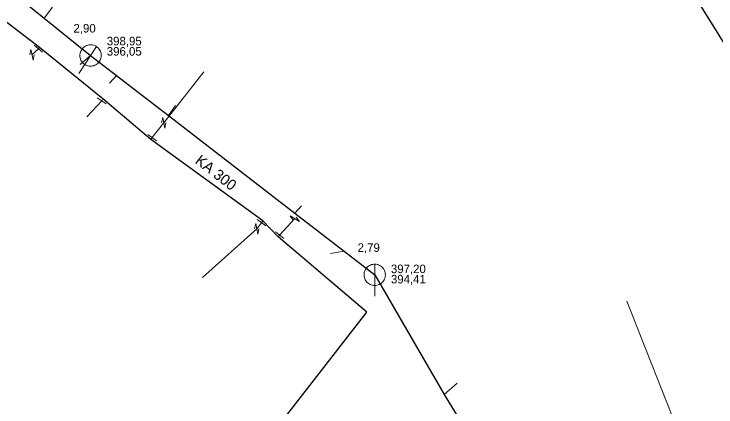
# Model space of a CAD drawing. Extents: x -809028 to -807737, y -990545 to -989489.
# Drawn here: x -808618 to -808552.3, y -989965.3 to -989928.5 of the extents above; entities that cross this region are included whole.
import ezdxf

# ---------------------------------------------------------------- set-up
doc = ezdxf.new("R2010")
doc.units = 0
doc.header["$LTSCALE"] = 0.32
for name, color, linetype, lineweight in [('1', 7, 'Continuous', 13), ('11', 7, 'Continuous', 13), ('13', 7, 'Continuous', 13), ('14', 7, 'Continuous', 25), ('17', 7, 'Continuous', 25), ('22', 7, 'Continuous', 13), ('34', 7, 'Continuous', 13), ('47', 7, 'Continuous', 13)]:
    doc.layers.add(name, color=color, linetype=linetype, lineweight=lineweight)

msp = doc.modelspace()

# ---------------------------------------------------------------- linework, layer by layer
at = {"layer": '11'}
for p, q in [((-808614.441, -989927.888), (-808615.221, -989928.912)), ((-808611.855, -989933.254), (-808610.879, -989932.412)), ((-808609.092, -989934.993), (-808608.456, -989934.281)), ((-808602.923, -989937.094), (-808603.589, -989938.035)), ((-808591.103, -989946.477), (-808591.739, -989947.173)), ((-808588.406, -989950.943), (-808587.127, -989950.728)), ((-808576.519, -989963.089), (-808577.742, -989964.137))]:
    msp.add_line(p, q, dxfattribs=at)
at = {"layer": '13'}
for p, q in [((-808615.761, -989931.774), (-808616.368, -989932.337)), ((-808604.02, -989938.699), (-808600.261, -989933.936)), ((-808609.837, -989936.655), (-808611.215, -989938.151)), ((-808593.163, -989949.223), (-808591.755, -989947.674)), ((-808594.868, -989948.063), (-808595.31, -989948.63)), ((-808595.31, -989948.63), (-808600.377, -989953.192))]:
    msp.add_line(p, q, dxfattribs=at)
for points in [[(-808605.107, -989940.09), (-808604.056, -989938.745), (-808604.02, -989938.699)], [(-808554.927, -989969.793), (-808555.077, -989969.458), (-808560.651, -989955.405)]]:
    msp.add_lwpolyline(points, dxfattribs=at)
at = {"layer": '14', "lineweight": 13}
for p, q in [((-808615.675, -989931.666), (-808615.761, -989931.774)), ((-808609.713, -989936.474), (-808609.837, -989936.655)), ((-808605.238, -989940.263), (-808605.107, -989940.09)), ((-808594.743, -989947.892), (-808594.868, -989948.063)), ((-808593.302, -989949.39), (-808593.163, -989949.223))]:
    msp.add_line(p, q, dxfattribs=at)
at = {"layer": '14'}
for points in [[(-808639.281, -989909.515), (-808629.598, -989917.322), (-808624.403, -989921.511), (-808615.221, -989928.912), (-808610.879, -989932.412)], [(-808610.879, -989932.412), (-808608.456, -989934.281), (-808603.589, -989938.035), (-808591.739, -989947.173), (-808587.127, -989950.728), (-808584.261, -989952.94)], [(-808584.261, -989952.94), (-808577.742, -989964.137), (-808576.188, -989966.702), (-808569.23, -989979.334)]]:
    msp.add_lwpolyline(points, dxfattribs=at)
at = {"layer": '17'}
for points in [[(-808597.027, -989858.141), (-808590.285, -989869.403), (-808588.355, -989872.717), (-808579.785, -989886.311), (-808576.531, -989891.473), (-808571.029, -989900.055), (-808568.32, -989904.55), (-808566.73, -989906.969), (-808565.989, -989908.23), (-808563.671, -989911.931), (-808563.097, -989912.848), (-808553.532, -989928.12), (-808547.531, -989937.702), (-808538.164, -989952.659), (-808533.093, -989960.754)], [(-808600.013, -989988.618), (-808601.767, -989983.94), (-808603.874, -989980.796), (-808595.03, -989969.311), (-808584.982, -989956.438), (-808593.302, -989949.39), (-808594.743, -989947.892), (-808605.238, -989940.263), (-808609.713, -989936.474), (-808615.675, -989931.666), (-808621.423, -989927.259), (-808628.477, -989921.605), (-808630.686, -989919.647), (-808638.669, -989911.952)]]:
    msp.add_lwpolyline(points, dxfattribs=at)
at = {"layer": '22'}
for p, q in [((-808611.968, -989934.089), (-808610.334, -989931.573)), ((-808584.261, -989954.94), (-808584.26, -989951.94))]:
    msp.add_line(p, q, dxfattribs=at)
for points in [[(-808610.04, -989932.956), (-808609.986, -989932.862), (-808609.942, -989932.761), (-808609.909, -989932.656), (-808609.888, -989932.55), (-808609.879, -989932.44), (-808609.882, -989932.331), (-808609.897, -989932.222), (-808609.924, -989932.116), (-808609.962, -989932.013), (-808610.011, -989931.916), (-808610.07, -989931.823), (-808610.14, -989931.739), (-808610.218, -989931.662), (-808610.304, -989931.594), (-808610.397, -989931.536), (-808610.495, -989931.489), (-808610.599, -989931.452), (-808610.705, -989931.427), (-808610.814, -989931.414), (-808610.923, -989931.413), (-808611.033, -989931.424), (-808611.139, -989931.447), (-808611.244, -989931.481), (-808611.343, -989931.526), (-808611.437, -989931.582), (-808611.524, -989931.648), (-808611.604, -989931.724), (-808611.675, -989931.807), (-808611.736, -989931.898), (-808611.787, -989931.995), (-808611.828, -989932.096), (-808611.856, -989932.202), (-808611.874, -989932.31), (-808611.879, -989932.419), (-808611.872, -989932.529), (-808611.853, -989932.637), (-808611.823, -989932.742), (-808611.781, -989932.843), (-808611.729, -989932.939), (-808611.666, -989933.029), (-808611.594, -989933.111), (-808611.513, -989933.185), (-808611.424, -989933.25), (-808611.329, -989933.304), (-808611.229, -989933.348), (-808611.125, -989933.381), (-808611.017, -989933.402), (-808610.908, -989933.411), (-808610.798, -989933.408), (-808610.69, -989933.394), (-808610.584, -989933.368), (-808610.481, -989933.329), (-808610.383, -989933.281), (-808610.292, -989933.221), (-808610.207, -989933.152), (-808610.129, -989933.074), (-808610.062, -989932.988)], [(-808583.261, -989952.94), (-808583.266, -989952.831), (-808583.284, -989952.723), (-808583.314, -989952.617), (-808583.354, -989952.516), (-808583.406, -989952.419), (-808583.468, -989952.329), (-808583.54, -989952.246), (-808583.62, -989952.172), (-808583.708, -989952.106), (-808583.802, -989952.051), (-808583.902, -989952.006), (-808584.007, -989951.973), (-808584.114, -989951.951), (-808584.223, -989951.941), (-808584.333, -989951.943), (-808584.441, -989951.957), (-808584.548, -989951.982), (-808584.651, -989952.019), (-808584.749, -989952.068), (-808584.841, -989952.126), (-808584.927, -989952.195), (-808585.004, -989952.272), (-808585.073, -989952.358), (-808585.132, -989952.45), (-808585.18, -989952.548), (-808585.217, -989952.651), (-808585.243, -989952.758), (-808585.257, -989952.866), (-808585.26, -989952.976), (-808585.25, -989953.085), (-808585.229, -989953.192), (-808585.195, -989953.296), (-808585.151, -989953.396), (-808585.096, -989953.491), (-808585.03, -989953.579), (-808584.956, -989953.659), (-808584.873, -989953.731), (-808584.783, -989953.793), (-808584.687, -989953.845), (-808584.585, -989953.886), (-808584.48, -989953.916), (-808584.372, -989953.934), (-808584.262, -989953.94), (-808584.153, -989953.934), (-808584.045, -989953.916), (-808583.94, -989953.887), (-808583.838, -989953.846), (-808583.741, -989953.794), (-808583.651, -989953.732), (-808583.568, -989953.661), (-808583.493, -989953.581), (-808583.428, -989953.493), (-808583.372, -989953.399), (-808583.328, -989953.299), (-808583.294, -989953.195), (-808583.272, -989953.087), (-808583.262, -989952.978)]]:
    msp.add_lwpolyline(points, close=True, dxfattribs=at)
at = {"layer": '34'}
for p, q in [((-808616.15, -989931.46), (-808615.371, -989932.088)), ((-808610.249, -989936.372), (-808609.425, -989936.938)), ((-808605.507, -989939.791), (-808604.706, -989940.389)), ((-808595.271, -989947.768), (-808594.464, -989948.358)), ((-808593.548, -989948.904), (-808592.777, -989949.541))]:
    msp.add_line(p, q, dxfattribs=at)
at = {"layer": '47'}
for p, q in [((-808616.466, -989931.837), (-808616.569, -989932.337)), ((-808604.118, -989938.199), (-808604.221, -989938.699)), ((-808592.19, -989947.41), (-808591.89, -989947.822)), ((-808595.408, -989948.13), (-808595.511, -989948.63))]:
    msp.add_line(p, q, dxfattribs=at)
for points in [[(-808616.466, -989931.837), (-808616.27, -989932.837), (-808616.167, -989932.337)], [(-808604.118, -989938.199), (-808603.922, -989939.199), (-808603.819, -989938.699)], [(-808592.19, -989947.41), (-808591.319, -989947.937), (-808591.619, -989947.525)], [(-808595.408, -989948.13), (-808595.212, -989949.13), (-808595.109, -989948.63)]]:
    msp.add_lwpolyline(points, dxfattribs=at)

# ---------------------------------------------------------------- texts
at = {"layer": '1'}
for s, p in [('2,90', (-808612.479, -989930.26)), ('2,79', (-808585.861, -989950.787))]:
    msp.add_text(s, height=0.8, dxfattribs=at).set_placement(p)
msp.add_text('KA 300', height=1, rotation=322, dxfattribs=at).set_placement((-808601.158, -989942.415))
at = {"layer": '14'}
for s, p in [('398,95', (-808609.358, -989931.464)), ('396,05', (-808609.358, -989932.424)), ('397,20', (-808582.739, -989952.779)), ('394,41', (-808582.739, -989953.739))]:
    msp.add_text(s, height=0.8, dxfattribs=at).set_placement(p)

doc.saveas('drawing.dxf')
